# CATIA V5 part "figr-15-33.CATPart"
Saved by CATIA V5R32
Part number: Part1
Bounding box of the stored display mesh (mm): x -40.264 to 42.014, y -25.445 to 25.445, z -51 to 0.75
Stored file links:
  D:\PROJECTS\Project 2022\CATIA V5 6R 2022\Resources\Part Files\c15_catia_v5_6r2022_prt\figr-15-33.CATPart
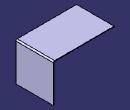
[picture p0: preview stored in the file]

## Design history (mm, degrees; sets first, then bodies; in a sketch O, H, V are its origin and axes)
SheetMetalParameters1: Thickness 0.75, BendRadius 1, KFactor 0.356492 {= log(min(100,max(20*SheetMetalParameters1.BendRadius,SheetMetalParameters1.Thickness)/SheetMetalParameters1.Thickness))/log(100)/2}, ReliefRadialLength 1, ReliefAxialLength 2, MinimumBendRadius 0
Body1 (main body)
  Sketch1 on xy-plane, origin (0, 0, 0), H (1, 0, 0), V (0, 1, 0)
    line L1 (-40.2643, 25.445) -> (40.2643, 25.445)
    line L2 (40.2643, 25.445) -> (40.2643, -25.445)
    line L3 (40.2643, -25.445) -> (-40.2643, -25.445)
    line L4 (-40.2643, -25.445) -> (-40.2643, 25.445)
    horizontal: L1 H, L3 H
    vertical: L2 V, L4 V
    symmetry: L1 L3 H, L4 L2 V
  Wall1: Thickness 0.75, Profile Sketch1
  Flange1: Angle 90, Length 50, Radius 1, KFacteur 0.356492 {= log(min(100,max(20*Flange1.Radius,SheetMetalParameters1.Thickness)/SheetMetalParameters1.Thickness))/log(100)/2}, Guide edge [face of Wall1 | face of Wall1]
